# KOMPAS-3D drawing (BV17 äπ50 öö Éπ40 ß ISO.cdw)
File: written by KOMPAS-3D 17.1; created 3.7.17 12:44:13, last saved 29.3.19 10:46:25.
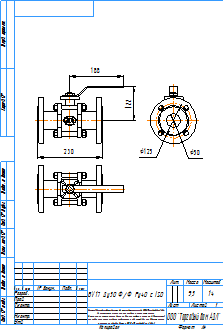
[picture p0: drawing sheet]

Sheet 1: A4, portrait

Title block, sheet 1: name: BV17 Ду50 Ф/Ф Ру40 с ISO; material: Сталь 20  ГОСТ 1050-88; mass: 9,5; sheets: 1; sheet format: A4; stored path: C:\Users\kka\KOMPAS_Work\!Trash\СС02 СС03 ФФ Смотровые стекла\СС01.cdw

Views: Спереди 1, Проекционный вид 2, Проекционный вид 3
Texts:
  Klimkovich
  ADL
  Рама для чертежей
  Лит-Масса-Масштаб
  Материал-Предприятие
  Масштаб
  Изм.
  Лист
  № докум.
  Подп.
  Дата
  Лит.
  Разраб.
  Пров.
  Т.контр.
  Листов
  Внимание! Данный продукт является объектом авторского права ООО «Торговый Дом АДЛ».
  Запрещается изменение, копирование, распространение
  (в том числе путем копирования на другие сайты и ресурсы в Интернете)
  или любое иное использование информации и объектов без предварительного
  согласия правообладателя (ООО «Торговый Дом АДЛ»).
  Н.контр.
  Утв.
  ООО "Торговый дом АДЛ"
  Изменение
  Номер документа
  Подпись
  Обозначение документа
  Наименование изделия
  Масса изделия по ГОСТ 2.109-73
  Порядковый номер листа
  Общее количество листов в документе
  Характер работы, выполненной лицом, подписавшим документ
  Наименование или индекс предприятия, выпускающего документ
  Инв. № подл.
  Подп. и дата
  Взам. инв. №
  Инв. № дубл.
  Инвентарный номер подлинника по ГОСТ 2.501-68
  Подпись принявшего подлинник в отдел технической документации
  Инвентарный номер подлинника, взамен которого выпущен данный подлинник
  Инвентарный номер дубликата по ГОСТ 2.502-68
  Подпись принявшего дубликат в отдел технической документации
  Справ. №
  Перв. примен.
  Обозначение документа, взамен или на основании которого выпущен данный документ
  Обозначение документа, в котором впервые записан данный документ
  Подпись лица, копировавшего чертеж
  Обозначение формата листа
  !Рама для чертежа
Dimensions and other numbers on the sheet: 188; 230; 122; 125; 50; 1:4; 1; 9,5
